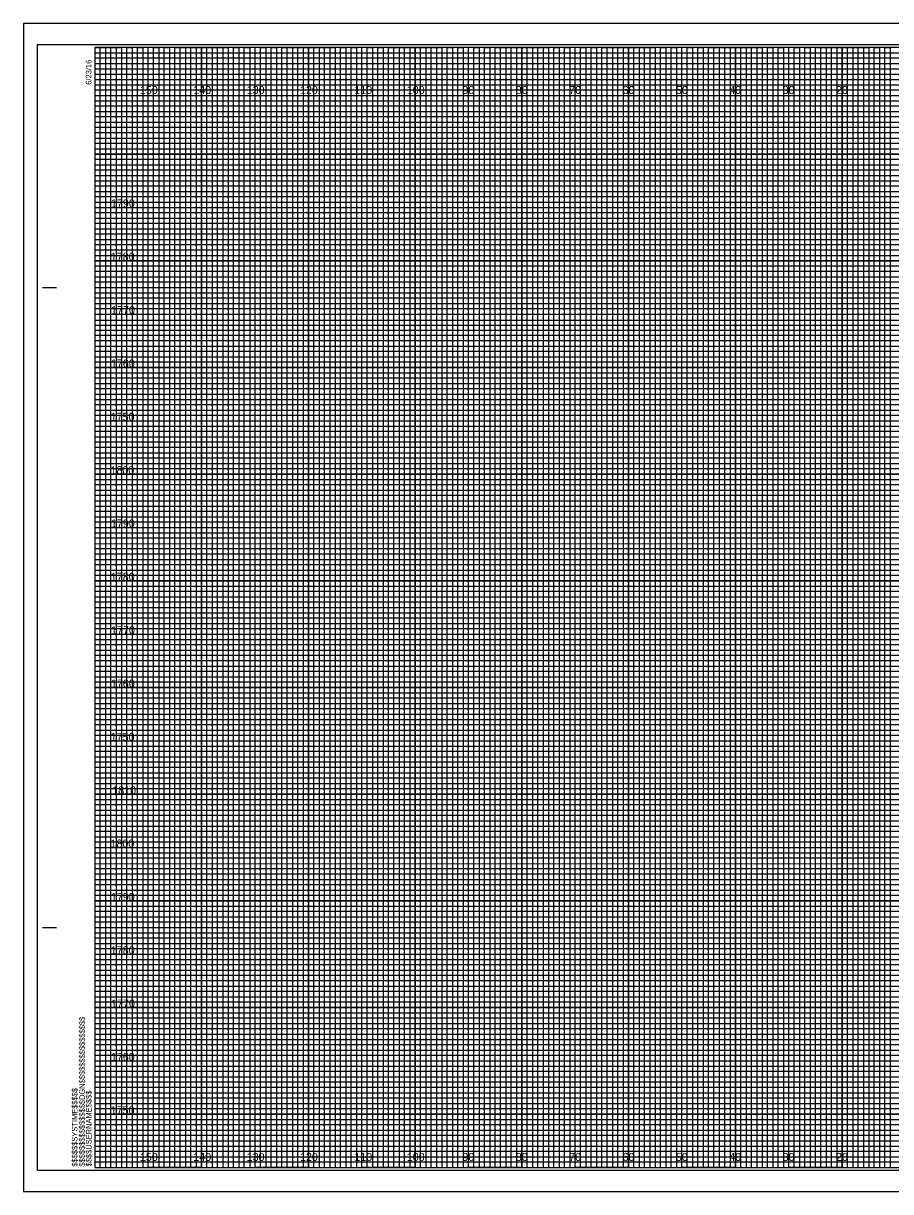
# Model space of a CAD drawing. Extents: x -13 to 323, y -5 to 874.
# Drawn here: x -13.4 to 149.1, y 215.5 to 434.5 of the extents above; entities that cross this region are included whole.
import ezdxf

# ---------------------------------------------------------------- set-up
doc = ezdxf.new("R2010")
doc.units = 0
for name, color, linetype in [('Prop XS DDE', 7, 'Continuous'), ('Prop XS DDE Elevations', 7, 'Continuous'), ('Prop XS DDE Slope Text', 7, 'Continuous'), ('Prop XS Gore Control Minimum', 7, 'Continuous'), ('Prop XS Shoulder Borrow Shape', 7, 'Continuous'), ('Raster_Level_0', 7, 'Continuous'), ('Scratch_Level_3', 7, 'Continuous'), ('Sheet Cutting Line CELL', 7, 'Continuous'), ('Sheet DOT Grid CELL', 7, 'Continuous'), ('Sheet Plot Border Inside CELL', 7, 'Continuous'), ('Sheet Plot Border Outside CELL', 7, 'Continuous')]:
    doc.layers.add(name, color=color, linetype=linetype)

msp = doc.modelspace()

# ---------------------------------------------------------------- linework, layer by layer
at = {"layer": 'Prop XS DDE'}
for p, q in [((0, 429), (260, 429)), ((260, 427.98), (0, 427.98)), ((0, 427.98), (0, 427)), ((0, 427), (260, 427)), ((260, 425.89), (0, 425.89)), ((0, 425.89), (0, 424)), ((0, 424), (320, 424))]:
    msp.add_line(p, q, dxfattribs=at)
for points in [[(0, 423), (270, 423), (320, 423), (320, 422), (0, 422)], [(0, 421), (320, 421), (320, 419), (0, 419)], [(0, 418), (320, 418), (320, 417), (0, 416.98)], [(0, 416), (320, 416), (320, 414), (0, 414)], [(0, 413), (320, 413), (320, 412), (0, 412)], [(0, 411), (320, 411), (320, 409), (0, 409)], [(0, 408), (320, 408), (320, 407), (0, 407)], [(0, 406), (320, 406), (320, 404), (0, 404)], [(0, 403), (320, 403), (320, 402), (0, 402)], [(0, 401), (320, 401), (320, 399), (0, 399)], [(0, 398), (320, 398), (320, 397), (0, 397)], [(0, 396), (320, 396), (320, 393.95), (320, 393), (320, 392), (0, 392)], [(0, 394), (320, 394), (320, 393), (0, 393)], [(0, 391), (320, 391), (320, 389), (0, 389.03)], [(0, 389.03), (320, 389), (320, 388), (0, 388)], [(0, 387), (320, 387), (320, 386), (0, 386)], [(0, 384), (320, 384), (320, 383), (0, 383)], [(0, 382), (320, 382), (320, 381), (0, 381)], [(-0.07, 378.89), (320, 378.89), (320, 377.88), (-0.07, 377.88)], [(0, 377), (320, 377), (320, 376), (0, 376)], [(0, 374), (320, 374), (320, 373), (0, 373)], [(0, 372), (320, 372), (320, 371), (0, 371)], [(0, 369), (320, 369), (320, 368), (0, 368)], [(0, 367), (320, 367), (320, 366), (0, 366)], [(0, 364), (320, 364), (320, 363), (0, 363)], [(0, 362), (320, 362), (320, 361), (0, 361)], [(0, 359), (320, 359), (319.99, 357.98), (0, 358)], [(0, 357), (320, 357), (320, 356), (0, 356)], [(0, 354), (320, 354), (320, 353), (0, 353)], [(0, 352), (320, 352), (320, 351), (0, 351)], [(0, 349), (320, 349), (320, 348), (0, 348)], [(0, 347), (320, 347), (320, 346), (0, 346)], [(0, 344), (320, 344), (320, 343), (0, 343)], [(0, 342), (320, 342), (320, 341), (0, 341)], [(0, 339), (320, 339), (320, 338), (0, 338)], [(0, 336.99), (320.07, 336.91), (320, 336), (0, 336)], [(0, 334), (320, 334), (320, 333), (0, 333)], [(0, 332), (320, 332), (320, 331), (0, 331)], [(0, 329), (320, 329), (320, 328), (0, 328)], [(0, 327), (320, 327), (320, 326), (0, 326)], [(0, 324), (320, 324), (320, 323), (0, 323)], [(0, 322), (320, 322), (320, 321), (0, 321)], [(0, 319), (320, 319), (320, 318), (0, 318)], [(0, 317), (320, 317), (320, 316), (0, 316)], [(0, 314), (320, 314), (320, 313), (0, 313)], [(0, 312), (320, 312), (320, 311), (0, 311)], [(0, 309), (320, 309), (320, 308), (0, 308)], [(0, 307), (320, 307), (320, 306), (0, 306)], [(0, 304), (320, 304), (320, 303), (0, 303)], [(0, 302), (320, 302), (320, 301), (0, 301)], [(0, 299), (320, 299), (319.99, 297.98), (0, 298)], [(0, 297), (320, 297), (320, 296), (0, 296)], [(0, 294), (320, 294), (320, 293), (0, 293)], [(0, 292), (320, 292), (320, 291), (0, 291)], [(0, 289), (320, 289), (320, 288), (0, 288)], [(0, 287), (320, 287), (320, 286), (0, 286)], [(0, 284), (320, 284), (320, 283), (0, 283)], [(0, 282), (320, 282), (320, 281), (0, 281)], [(0, 279), (320, 279), (320, 278), (0, 278)], [(0, 276.99), (320.07, 276.91), (320, 276), (0, 276)], [(0, 274), (320, 274), (320, 273), (0, 273)], [(0, 272), (320, 272), (320, 271), (0, 271)], [(0, 269), (320, 269), (320, 268), (0, 268)], [(0, 267), (320, 267), (320, 266), (0, 266)], [(0, 264), (320, 264), (320, 263), (0, 263)], [(0, 262), (320, 262), (320, 261), (0, 261)], [(0, 259), (320, 259), (320, 258), (0, 258)], [(0, 257), (320, 257), (320, 256), (0, 256)], [(0, 254), (320, 254), (320, 253), (0, 253)], [(0, 252), (320, 252), (320, 251), (0, 251)], [(0, 249), (320, 249), (320, 248), (0, 248)], [(0, 247), (320, 247), (320, 246), (0, 246)], [(0, 244), (320, 244), (320, 243), (0, 243)], [(0, 242), (320, 242), (320, 241), (0, 241)], [(0, 239), (320, 239), (320, 238), (0, 238)], [(0, 237), (320, 237), (320, 236), (0, 236)], [(0, 234), (320, 234), (320, 233), (0, 233)], [(0, 232), (320, 232), (320, 231), (0, 231)], [(0, 229), (320, 229), (320, 228), (0, 228)], [(0, 227), (320, 227), (320, 226), (0, 226)], [(0, 224), (320, 224), (320, 223), (0, 223)], [(0, 222), (320, 222), (320, 221), (0, 221)]]:
    msp.add_lwpolyline(points, dxfattribs=at)
at = {"layer": 'Prop XS DDE Elevations'}
for points in [[(0, 220), (1, 220), (1, 430), (2, 430), (2, 220)], [(2, 220), (3, 220), (3, 430), (4, 430), (4, 220)], [(5, 220), (6, 220), (6, 430), (7, 430), (7, 220)], [(7, 220), (8, 220), (8, 430), (9, 430), (9, 220)], [(10, 220), (11, 220), (11, 430), (12, 430), (12, 220)], [(12, 220), (13, 220), (13, 430), (14, 430), (14, 220)], [(15, 220), (16, 220), (16, 430), (17, 430), (17, 220)], [(17, 220), (18, 220), (18, 430), (19, 430), (19, 220)], [(20, 220), (21, 220), (21, 430), (22, 430), (22, 220)], [(22, 220), (23, 220), (23, 430), (24, 430), (24, 220)], [(25, 220), (26, 220), (26, 430), (27, 430), (27, 220)], [(27, 220), (28, 220), (28, 430), (29, 430), (29, 220)], [(30, 220), (31, 220), (31, 430), (32, 430), (32, 220)], [(32, 220), (33, 220), (33, 430), (34, 430), (34, 220)], [(35, 220), (36, 220), (36, 430), (37, 430), (37, 220)], [(37, 220), (38, 220), (38, 430), (39, 430), (39, 220)], [(40, 220), (41, 220), (41, 430), (42, 430), (42, 220)], [(42, 220), (43, 220), (43, 430), (44, 430), (44, 220)], [(45, 220), (46, 220), (46, 430), (47, 430), (47, 220)], [(47, 220), (48, 220), (48, 430), (49, 430), (49, 220)], [(50, 220), (51, 220), (51, 430), (52, 430), (52, 220)], [(52, 220), (53, 220), (53, 430), (54, 430), (54, 220)], [(55, 220), (56, 220), (56, 430), (57, 430), (57, 220)], [(57, 220), (58, 220), (58, 430), (59, 430), (59, 220)], [(60, 220), (61, 220), (61, 430), (62, 430), (62, 220)], [(62, 220), (63, 220), (63, 430), (64, 430), (64, 220)], [(65, 220), (66, 220), (66, 430), (67, 430), (67, 220)], [(67, 220), (68, 220), (68, 430), (69, 430), (69, 220)], [(70, 220), (71, 220), (71, 430), (72, 430), (72, 220)], [(72, 220), (73, 220), (73, 430), (74, 430), (74, 220)], [(75, 220), (76, 220), (76, 430), (77, 430), (77, 220)], [(77, 220), (78, 220), (78, 430), (79, 430), (79, 220)], [(80, 220), (81, 220), (81, 430), (82, 430), (82, 220)], [(82, 220), (83, 220), (83, 430), (84, 430), (84, 220)], [(85, 220), (86, 220), (86, 430), (87, 430), (87, 220)], [(87, 220), (88, 220), (88, 430), (89, 430), (89, 220)], [(90, 220), (91, 220), (91, 430), (92, 430), (92, 220)], [(92, 220), (93, 220), (93, 430), (94, 430), (94, 220)], [(95, 220), (96, 220), (96, 430), (97, 430), (97, 220)], [(97, 220), (98, 220), (98, 430), (99, 430), (99, 220)], [(100, 220), (101, 220), (101, 430), (102, 430), (102, 220)], [(102, 220), (103, 220), (103, 430), (104, 430), (104, 220)], [(105, 220), (106, 220), (106, 430), (107, 430), (107, 220)], [(107, 220), (108, 220), (108, 430), (109, 430), (109, 220)], [(110, 220), (111, 220), (111, 430), (112, 430), (112, 220)], [(112, 220), (113, 220), (113, 430), (114, 430), (114, 220)], [(115, 220), (116, 220), (116, 430), (117, 430), (117, 220)], [(117, 220), (118, 220), (118, 430), (119, 430), (119, 220)], [(120, 220), (121, 220), (121, 430), (122, 430), (122, 220)], [(122, 220), (123, 220), (123, 430), (124, 430), (124, 220)], [(125, 220), (126, 220), (126, 430), (127, 430), (127, 220)], [(127, 220), (128, 220), (128, 430), (129, 430), (129, 220)], [(130, 220), (131, 220), (131, 430), (132, 430), (132, 220)], [(132, 220), (133, 220), (133, 430), (134, 430), (134, 220)], [(135, 220), (136, 220), (136, 430), (137, 430), (137, 220)], [(137, 220), (138, 220), (138, 430), (139, 430), (139, 220)], [(140, 220), (141, 220), (141, 430), (142, 430), (142, 220)], [(142, 220), (143, 220), (143, 430), (144, 430), (144, 220)], [(145, 220), (146, 220), (146, 430), (147, 430), (147, 220)], [(147, 220), (148, 220), (148, 430), (149, 430), (149, 220)]]:
    msp.add_lwpolyline(points, dxfattribs=at)
at = {"layer": 'Prop XS DDE Slope Text'}
for p, q in [((-9.8, 385), (-7.3, 385)), ((-9.7, 385), (-7.2, 385)), ((-9.8, 265), (-7.3, 265)), ((-9.7, 265), (-7.2, 265)), ((0, 220), (0, 220)), ((0, 220), (0, 220)), ((0, 220), (0, 220)), ((0, 220), (0, 220)), ((0, 220), (0, 220)), ((0, 220), (0, 220)), ((0, 220), (0, 220))]:
    msp.add_line(p, q, dxfattribs=at)
msp.add_lwpolyline([(320, 430), (0, 430), (0, 220), (320, 220)], close=True, dxfattribs=at)
at = {"layer": 'Prop XS Gore Control Minimum'}
for p, q in [((10, 430), (0, 430)), ((10, 220), (10, 430)), ((30, 430), (20, 430)), ((20, 430), (20, 220)), ((30, 220), (30, 430)), ((50, 430), (40, 430)), ((40, 430), (40, 220)), ((50, 220), (50, 430)), ((70, 430), (60, 430)), ((60, 430), (60, 220)), ((70, 220), (70, 430)), ((90, 430), (80, 430)), ((80, 430), (80, 220)), ((90, 220), (90, 430)), ((110, 430), (100, 430)), ((100, 430), (100, 220)), ((110, 220), (110, 430)), ((130, 430), (120, 430)), ((120, 430), (120, 220)), ((130, 220), (130, 430)), ((150, 430), (140, 430)), ((140, 430), (140, 220)), ((20, 220), (10, 220)), ((40, 220), (30, 220)), ((60, 220), (50, 220)), ((80, 220), (70, 220)), ((100, 220), (90, 220)), ((120, 220), (110, 220)), ((140, 220), (130, 220))]:
    msp.add_line(p, q, dxfattribs=at)
for points in [[(0, 420), (320, 420), (320, 410), (0, 410)], [(0, 400), (320, 400), (320, 390), (0, 390)], [(0, 380), (320, 380), (320, 370), (0, 370)], [(0, 360), (320, 360), (320, 350), (0, 350)], [(0, 340), (320, 340), (320, 330), (0, 330)], [(0, 320), (320, 320), (320, 310), (0, 310)], [(0, 300), (320, 300), (320, 290), (0, 290)], [(0, 280), (320, 280), (320, 270), (0, 270)], [(0, 260), (320, 260), (320, 250), (0, 250)], [(0, 240), (320, 240), (320, 230), (0, 230)]]:
    msp.add_lwpolyline(points, dxfattribs=at)
at = {"layer": 'Prop XS Shoulder Borrow Shape'}
for points in [[(0, 430), (5, 430), (5, 220), (15, 220), (15, 430), (25, 430), (25, 220), (35, 220), (35, 430), (45, 430), (45, 220), (55, 220), (55, 430), (65, 430), (65, 220), (75, 220), (75, 430), (85, 430), (85, 220), (95, 220), (95, 430), (105, 430), (105, 220), (115, 220), (115, 430), (125, 430), (125, 220), (135, 220), (135, 430), (145, 430), (145, 220), (155, 220)], [(0, 425), (275, 425)], [(0, 405), (320, 405), (320, 415), (0, 415)], [(0, 385), (320, 385), (320, 395), (0, 395)], [(0, 365), (320, 365), (320, 375), (0, 375)], [(0, 345), (320, 345), (320, 355), (0, 355)], [(0, 325), (320, 325), (320, 335), (0, 335)], [(0, 305), (320, 305), (320, 315), (0, 315)], [(0, 285), (320, 285), (320, 295), (0, 295)], [(0, 265), (320, 265), (320, 275), (0, 275)], [(0, 245), (320, 245), (320, 255), (0, 255)], [(0, 225), (320, 225), (320, 235), (0, 235)]]:
    msp.add_lwpolyline(points, dxfattribs=at)
at = {"layer": 'Sheet Cutting Line CELL'}
for p, q in [((323.3, 434.5), (-13.4, 434.5)), ((-13.4, 434.5), (-13.4, 215.5)), ((-13.4, 215.5), (323.3, 215.5))]:
    msp.add_line(p, q, dxfattribs=at)
at = {"layer": 'Sheet DOT Grid CELL'}
for p, q in [((10, 220), (10, 430)), ((20, 220), (20, 430)), ((30, 220), (30, 430)), ((40, 220), (40, 430)), ((50, 220), (50, 430)), ((60, 220), (60, 430)), ((70, 220), (70, 430)), ((80, 220), (80, 430)), ((90, 220), (90, 430)), ((100, 220), (100, 430)), ((110, 220), (110, 430)), ((120, 220), (120, 430)), ((130, 220), (130, 430)), ((140, 220), (140, 430)), ((0, 420), (320, 420)), ((0, 410), (320, 410)), ((0, 400), (320, 400)), ((0, 390), (320, 390)), ((0, 380), (320, 380)), ((0, 370), (320, 370)), ((0, 360), (320, 360)), ((0, 350), (320, 350)), ((0, 340), (320, 340)), ((0, 330), (320, 330)), ((0, 320), (320, 320)), ((0, 310), (320, 310)), ((0, 300), (320, 300)), ((0, 290), (320, 290)), ((0, 280), (320, 280)), ((0, 270), (320, 270)), ((0, 260), (320, 260)), ((0, 250), (320, 250)), ((0, 240), (320, 240)), ((0, 230), (320, 230))]:
    msp.add_line(p, q, dxfattribs=at)
at = {"layer": 'Sheet Plot Border Inside CELL'}
msp.add_lwpolyline([(-10.8, 219.5), (322.4, 219.5), (322.4, 430.5), (-10.8, 430.5)], close=True, dxfattribs=at)
at = {"layer": 'Sheet Plot Border Outside CELL'}
msp.add_lwpolyline([(-13.4, 215.5), (323.3, 215.5), (323.3, 434.5), (-13.4, 434.5)], close=True, dxfattribs=at)

# ---------------------------------------------------------------- texts
at = {"layer": 'Prop XS DDE Slope Text'}
for s, p in [('6/23/16', (-0.65, 423)), ('$$$$$$$$$$$$$$$$DGN$$$$$$$$$$$$$$$$', (-1.88, 220.18)), ('$$$$$$SYSTIME$$$$$', (-3.26, 220.18)), ('$$$$USERNAME$$$$', (-0.62, 220.23))]:
    msp.add_text(s, height=1.05, rotation=90, dxfattribs=at).set_placement(p)
at = {"layer": 'Raster_Level_0'}
for s, p in [('150', (8.44, 421.25)), ('140', (18.44, 421.25)), ('130', (28.44, 421.25)), ('120', (38.44, 421.25)), ('110', (48.62, 421.25)), ('100', (58.44, 421.25)), ('90', (68.86, 421.25)), ('80', (78.86, 421.25)), ('70', (88.86, 421.25)), ('60', (98.86, 421.25)), ('50', (108.86, 421.25)), ('40', (118.86, 421.25)), ('30', (128.86, 421.25)), ('20', (138.86, 421.25)), ('150', (8.44, 221.25)), ('140', (18.44, 221.25)), ('130', (28.44, 221.25)), ('120', (38.44, 221.25)), ('110', (48.62, 221.25)), ('100', (58.44, 221.25)), ('90', (68.86, 221.25)), ('80', (78.86, 221.25)), ('70', (88.86, 221.25)), ('60', (98.86, 221.25)), ('50', (108.86, 221.25)), ('40', (118.86, 221.25)), ('30', (128.86, 221.25)), ('20', (138.86, 221.25))]:
    msp.add_text(s, height=1.5, dxfattribs=at).set_placement(p)
at = {"layer": 'Scratch_Level_3'}
for s, p in [('1790', (3, 400)), ('1780', (2.98, 390)), ('1770', (3.04, 380)), ('1760', (3, 370)), ('1750', (2.96, 360)), ('1800', (2.92, 350)), ('1790', (3, 340)), ('1780', (2.98, 330)), ('1770', (3.04, 320)), ('1760', (3, 310)), ('1750', (2.96, 300)), ('1810', (3.25, 290)), ('1800', (2.92, 280)), ('1790', (3, 270)), ('1780', (2.98, 260)), ('1770', (3.04, 250)), ('1760', (3, 240)), ('1750', (2.96, 230))]:
    msp.add_text(s, height=1.5, dxfattribs=at).set_placement(p)

doc.saveas('drawing.dxf')
